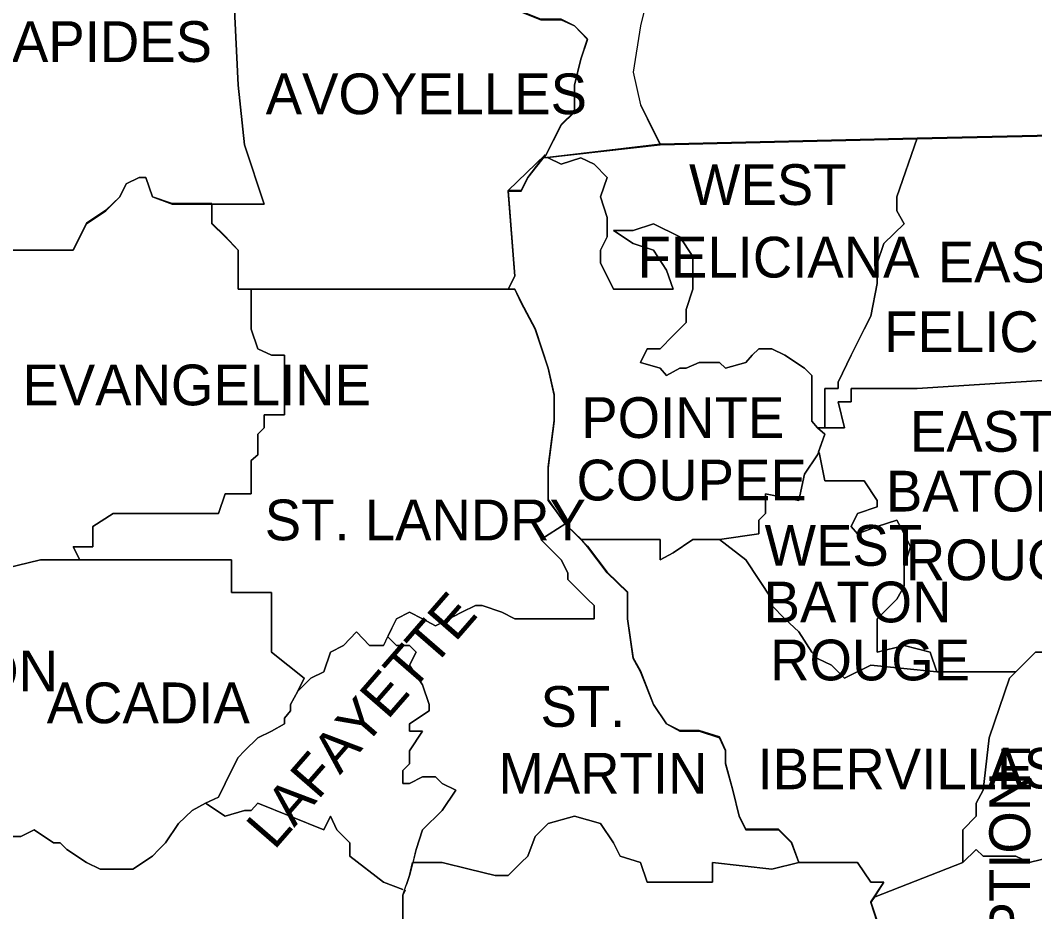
# Model space of a CAD drawing. Extents: x 0.19 to 2.82, y 0.04 to 1.79.
# Drawn here: x 2.3204 to 2.4368, y 1.4916 to 1.594 of the extents above; entities that cross this region are included whole.
import ezdxf

# ---------------------------------------------------------------- set-up
doc = ezdxf.new("R2010")
doc.units = 0
for name, color, linetype in [('Dist03', 7, 'Continuous'), ('Dist08', 7, 'Continuous'), ('Dist58', 7, 'Continuous'), ('Dist61', 7, 'Continuous'), ('Standard Info', 7, 'Continuous')]:
    doc.layers.add(name, color=color, linetype=linetype)

msp = doc.modelspace()

# ---------------------------------------------------------------- linework, layer by layer
at = {"layer": 'Dist03'}
for points in [[(2.3469, 1.56308), (2.3454, 1.56308), (2.3454, 1.56758), (2.3439, 1.56917), (2.3424, 1.57067), (2.3424, 1.57292), (2.34015, 1.57292), (2.33782, 1.57292), (2.33557, 1.57367), (2.33482, 1.57592), (2.33407, 1.57592), (2.33257, 1.57517), (2.33182, 1.57367), (2.33024, 1.57217), (2.32799, 1.57067), (2.32649, 1.56758), (2.31899, 1.56758)], [(2.37715, 1.56308), (2.3469, 1.56308)], [(2.3829, 1.53617), (2.38099, 1.53892), (2.38099, 1.54267), (2.38165, 1.548), (2.38165, 1.551), (2.38099, 1.554), (2.37949, 1.55858), (2.3779, 1.56158), (2.37715, 1.56308)], [(2.40974, 1.49725), (2.4089, 1.49958), (2.4074, 1.50108), (2.40365, 1.50108), (2.4029, 1.50258), (2.40215, 1.50558), (2.40132, 1.50867), (2.40132, 1.51017), (2.40065, 1.51167), (2.39832, 1.51242), (2.39607, 1.51242), (2.39457, 1.51317), (2.39307, 1.51542), (2.39157, 1.51925), (2.39074, 1.52075), (2.39007, 1.52525), (2.39007, 1.52833), (2.38774, 1.53058), (2.38549, 1.53358), (2.38474, 1.53433)], [(2.41899, 1.48975), (2.41799, 1.49275), (2.41949, 1.495), (2.41799, 1.495), (2.41649, 1.49725), (2.40974, 1.49725)]]:
    msp.add_lwpolyline(points, dxfattribs=at)
at = {"layer": 'Dist08'}
for points in [[(2.38057, 1.57817), (2.38249, 1.582), (2.38399, 1.5835), (2.38399, 1.5865), (2.38474, 1.5895), (2.38549, 1.59183), (2.38399, 1.59333), (2.38249, 1.59408), (2.38015, 1.59408), (2.3764, 1.59558), (2.37415, 1.59783), (2.37349, 1.59875)], [(2.3764, 1.57442), (2.3779, 1.57442), (2.37865, 1.57592), (2.38065, 1.5785)], [(2.30232, 1.56758), (2.32649, 1.56758), (2.32799, 1.57067), (2.33024, 1.57217), (2.33182, 1.57367), (2.33257, 1.57517), (2.33407, 1.57592), (2.33482, 1.57592), (2.33557, 1.57367), (2.33782, 1.57292), (2.34015, 1.57292), (2.3424, 1.57292)], [(2.3764, 1.56308), (2.37715, 1.56458), (2.3764, 1.57442)], [(2.3424, 1.57292), (2.3424, 1.57067), (2.3439, 1.56917), (2.3454, 1.56758), (2.3454, 1.56308), (2.3764, 1.56308)]]:
    msp.add_lwpolyline(points, dxfattribs=at)
at = {"layer": 'Dist58'}
for points in [[(2.40882, 1.63942), (2.40665, 1.63567), (2.40515, 1.63192), (2.40515, 1.62808), (2.40215, 1.62508), (2.39982, 1.62058), (2.39982, 1.613), (2.39907, 1.61), (2.39757, 1.60692), (2.39682, 1.60467), (2.39457, 1.60092), (2.39307, 1.59942), (2.39157, 1.59333), (2.39074, 1.588), (2.39157, 1.58425), (2.39232, 1.58275), (2.39382, 1.57975)], [(2.38057, 1.57817), (2.38249, 1.582), (2.38399, 1.5835), (2.38399, 1.5865), (2.38474, 1.5895), (2.38549, 1.59183), (2.38399, 1.59333), (2.38249, 1.59408), (2.38015, 1.59408), (2.3764, 1.59558), (2.37415, 1.59783), (2.37349, 1.59875)], [(2.39382, 1.57975), (2.38057, 1.57817)]]:
    msp.add_lwpolyline(points, dxfattribs=at)
at = {"layer": 'Dist61'}
msp.add_line((2.3764, 1.57442), (2.38065, 1.5785), dxfattribs=at)
for points in [[(2.44915, 1.581), (2.42332, 1.58042)], [(2.39382, 1.57975), (2.38057, 1.57817)], [(2.42332, 1.58042), (2.39382, 1.57975)], [(2.38065, 1.5785), (2.37865, 1.57592), (2.3779, 1.57442), (2.3764, 1.57442)], [(2.38049, 1.57825), (2.37865, 1.57592), (2.3779, 1.57442), (2.3764, 1.57442)], [(2.3764, 1.57442), (2.37715, 1.56458), (2.3764, 1.56308)], [(2.37715, 1.56308), (2.3779, 1.56158), (2.37949, 1.55858), (2.38099, 1.554), (2.38165, 1.551), (2.38165, 1.548), (2.38099, 1.54267), (2.38099, 1.53892), (2.3829, 1.53617)], [(2.38299, 1.53617), (2.38324, 1.53583), (2.38482, 1.53433)], [(2.38474, 1.53433), (2.38549, 1.53358), (2.38774, 1.53058), (2.39007, 1.52833), (2.39007, 1.52525), (2.39074, 1.52075), (2.39157, 1.51925), (2.39307, 1.51542), (2.39457, 1.51317), (2.39607, 1.51242), (2.39832, 1.51242), (2.40065, 1.51167), (2.40132, 1.51017), (2.40132, 1.50867), (2.40215, 1.50558), (2.4029, 1.50258), (2.40365, 1.50108), (2.4074, 1.50108), (2.4089, 1.49958), (2.40974, 1.49725)], [(2.40974, 1.49725), (2.41649, 1.49725), (2.41799, 1.495), (2.41949, 1.495), (2.41799, 1.49275), (2.41899, 1.48975)]]:
    msp.add_lwpolyline(points, dxfattribs=at)
at = {"layer": 'Standard Info'}
for p, q in [((2.42332, 1.58042), (2.42332, 1.58033)), ((2.37715, 1.56308), (2.3764, 1.56308)), ((2.38482, 1.53433), (2.38474, 1.53433))]:
    msp.add_line(p, q, dxfattribs=at)
for points in [[(2.40882, 1.63942), (2.40665, 1.63567), (2.40515, 1.63183), (2.40515, 1.62808), (2.40215, 1.62508), (2.39982, 1.6205), (2.39982, 1.61292), (2.39907, 1.60992), (2.39757, 1.60692), (2.39682, 1.60458), (2.39457, 1.60083), (2.39307, 1.59933), (2.39157, 1.59333), (2.39074, 1.588), (2.39157, 1.58425), (2.39232, 1.58267), (2.39382, 1.57967)], [(2.35815, 1.605), (2.35374, 1.60233), (2.35224, 1.60158), (2.35074, 1.60158), (2.3499, 1.60158), (2.3484, 1.60392), (2.3469, 1.60392), (2.3454, 1.60233), (2.34465, 1.60233), (2.3454, 1.5865), (2.34615, 1.57967), (2.3484, 1.57283), (2.3424, 1.57283)], [(2.3424, 1.57283), (2.3484, 1.57283), (2.34615, 1.57967), (2.3454, 1.5865), (2.34465, 1.60233), (2.3454, 1.60233), (2.3469, 1.60392), (2.3484, 1.60392), (2.3499, 1.60158), (2.35074, 1.60158), (2.35224, 1.60158), (2.35374, 1.60233), (2.35815, 1.605)], [(2.35815, 1.605), (2.35982, 1.60392), (2.36132, 1.60158), (2.36207, 1.60008), (2.36357, 1.59858), (2.36432, 1.59708), (2.36582, 1.59633), (2.36732, 1.59783), (2.36657, 1.59933), (2.36807, 1.60083), (2.3719, 1.60083), (2.37415, 1.59783), (2.3764, 1.5955), (2.38015, 1.594), (2.38249, 1.594), (2.38399, 1.59333), (2.38549, 1.59175), (2.38474, 1.5895), (2.38399, 1.5865), (2.38399, 1.58342), (2.38249, 1.58192), (2.38065, 1.57833)], [(2.38057, 1.57817), (2.38249, 1.58192), (2.38399, 1.58342), (2.38399, 1.5865), (2.38474, 1.5895), (2.38549, 1.59175), (2.38399, 1.59333), (2.38249, 1.594), (2.38015, 1.594), (2.3764, 1.5955), (2.37415, 1.59783), (2.37349, 1.59867)], [(2.42332, 1.58033), (2.44915, 1.58092)], [(2.39382, 1.57967), (2.38057, 1.57817)], [(2.38057, 1.57817), (2.39382, 1.57967)], [(2.39382, 1.57967), (2.42332, 1.58033)], [(2.42332, 1.58042), (2.42099, 1.57367), (2.42099, 1.57208), (2.42182, 1.57058), (2.41949, 1.56833), (2.41874, 1.56608), (2.41874, 1.56375), (2.41799, 1.56), (2.41724, 1.5585), (2.41574, 1.5555), (2.41424, 1.55242), (2.41424, 1.55167), (2.41274, 1.55167), (2.41274, 1.54942), (2.41274, 1.54717)], [(2.41274, 1.54717), (2.41274, 1.54942), (2.41274, 1.55167), (2.41424, 1.55167), (2.41424, 1.55242), (2.41574, 1.5555), (2.41724, 1.5585), (2.41799, 1.56), (2.41874, 1.56375), (2.41874, 1.56608), (2.41949, 1.56833), (2.42182, 1.57058), (2.42099, 1.57208), (2.42099, 1.57367), (2.42332, 1.58042)], [(2.38065, 1.57842), (2.37865, 1.57592), (2.3779, 1.57433), (2.3764, 1.57433)], [(2.3764, 1.57433), (2.3779, 1.57433), (2.37865, 1.57592), (2.38049, 1.57825)], [(2.38774, 1.57133), (2.38699, 1.57367), (2.38774, 1.57592), (2.38624, 1.57742), (2.38474, 1.57817), (2.38249, 1.57742), (2.38099, 1.57817)], [(2.38099, 1.57817), (2.38249, 1.57742), (2.38474, 1.57817), (2.38624, 1.57742), (2.38774, 1.57592), (2.38699, 1.57367), (2.38774, 1.57133)], [(2.3424, 1.57283), (2.34015, 1.57283), (2.33782, 1.57283), (2.33557, 1.57367), (2.33482, 1.57592), (2.33407, 1.57592), (2.33257, 1.57517), (2.33182, 1.57367), (2.33024, 1.57208), (2.32799, 1.57058), (2.32649, 1.56758), (2.30232, 1.56758)], [(2.31899, 1.56758), (2.32649, 1.56758), (2.32799, 1.57058), (2.33024, 1.57208), (2.33182, 1.57367), (2.33257, 1.57517), (2.33407, 1.57592), (2.33482, 1.57592), (2.33557, 1.57367), (2.33782, 1.57283), (2.34015, 1.57283), (2.3424, 1.57283), (2.3424, 1.57058), (2.3439, 1.56908), (2.3454, 1.56758), (2.3454, 1.56308), (2.3469, 1.56308)], [(2.3764, 1.57433), (2.37715, 1.56458), (2.3764, 1.56308)], [(2.3764, 1.56308), (2.37715, 1.56458), (2.3764, 1.57433)], [(2.3764, 1.56308), (2.3454, 1.56308), (2.3454, 1.56758), (2.3439, 1.56908), (2.3424, 1.57058), (2.3424, 1.57283)], [(2.38849, 1.56983), (2.39074, 1.56833), (2.39307, 1.56758), (2.39457, 1.56525), (2.39532, 1.56308), (2.39382, 1.56308), (2.39007, 1.56308), (2.38849, 1.56308), (2.38774, 1.56458), (2.38699, 1.56608), (2.38699, 1.56758), (2.38774, 1.56908), (2.38774, 1.57133)], [(2.38774, 1.57133), (2.38774, 1.56908), (2.38699, 1.56758), (2.38699, 1.56608), (2.38774, 1.56458), (2.38849, 1.56308), (2.39007, 1.56308), (2.39382, 1.56308), (2.39532, 1.56308), (2.39457, 1.56525), (2.39307, 1.56758), (2.39074, 1.56833), (2.38849, 1.56983)], [(2.4119, 1.54717), (2.41124, 1.54792), (2.41124, 1.55017), (2.41124, 1.55317), (2.4104, 1.554), (2.40815, 1.5555), (2.40665, 1.55625), (2.40515, 1.55625), (2.4044, 1.5555), (2.40365, 1.55467), (2.40132, 1.554), (2.40065, 1.55467), (2.39832, 1.55467), (2.39682, 1.554), (2.39607, 1.554), (2.39457, 1.55317), (2.39382, 1.554), (2.39157, 1.55467), (2.39232, 1.55625), (2.39382, 1.55625), (2.39532, 1.55775), (2.39682, 1.55925), (2.39682, 1.56075), (2.39757, 1.56308), (2.39757, 1.56683), (2.39607, 1.56908), (2.39307, 1.57058), (2.39074, 1.56983), (2.38849, 1.56983)], [(2.38849, 1.56983), (2.39074, 1.56983), (2.39307, 1.57058), (2.39607, 1.56908), (2.39757, 1.56683), (2.39757, 1.56308), (2.39682, 1.56075), (2.39682, 1.55925), (2.39532, 1.55775), (2.39382, 1.55625), (2.39232, 1.55625), (2.39157, 1.55467), (2.39382, 1.554), (2.39457, 1.55317), (2.39607, 1.554), (2.39682, 1.554), (2.39832, 1.55467), (2.40065, 1.55467), (2.40132, 1.554), (2.40365, 1.55467), (2.4044, 1.5555), (2.40515, 1.55625), (2.40665, 1.55625), (2.40815, 1.5555), (2.4104, 1.554), (2.41124, 1.55317), (2.41124, 1.55017), (2.41124, 1.54792), (2.4119, 1.54717), (2.41274, 1.54642), (2.4119, 1.54408), (2.4104, 1.54183), (2.40974, 1.53883), (2.4059, 1.53958), (2.4059, 1.53733), (2.40515, 1.53658), (2.40515, 1.535), (2.40065, 1.53433)], [(2.3469, 1.56308), (2.3469, 1.5585), (2.34765, 1.55625), (2.34924, 1.5555), (2.35074, 1.5555), (2.35074, 1.54867), (2.3484, 1.54867), (2.3484, 1.54717), (2.34765, 1.54642), (2.34765, 1.54408), (2.3469, 1.54342), (2.3469, 1.53958), (2.3439, 1.53958), (2.34315, 1.53733), (2.33107, 1.53733), (2.32874, 1.53583), (2.32874, 1.5335), (2.32649, 1.5335), (2.32724, 1.532)], [(2.32724, 1.532), (2.32649, 1.5335), (2.32874, 1.5335), (2.32874, 1.53583), (2.33107, 1.53733), (2.34315, 1.53733), (2.3439, 1.53958), (2.3469, 1.53958), (2.3469, 1.54342), (2.34765, 1.54408), (2.34765, 1.54642), (2.3484, 1.54717), (2.3484, 1.54867), (2.35074, 1.54867), (2.35074, 1.5555), (2.34924, 1.5555), (2.34765, 1.55625), (2.3469, 1.5585), (2.3469, 1.56308)], [(2.3469, 1.56308), (2.37715, 1.56308)], [(2.37715, 1.56308), (2.3779, 1.5615), (2.37949, 1.5585), (2.38099, 1.554), (2.38165, 1.55092), (2.38165, 1.54792), (2.38099, 1.54258), (2.38099, 1.53883), (2.3829, 1.53617)], [(2.38474, 1.53433), (2.38324, 1.53583), (2.38099, 1.53883), (2.38099, 1.54258), (2.38165, 1.54792), (2.38165, 1.55092), (2.38099, 1.554), (2.37949, 1.5585), (2.3779, 1.5615), (2.37715, 1.56308)], [(2.4119, 1.54717), (2.41499, 1.54717), (2.41424, 1.55017), (2.41574, 1.55017), (2.41574, 1.55167), (2.42332, 1.55167), (2.43465, 1.55242), (2.44674, 1.55317)], [(2.44674, 1.55317), (2.43465, 1.55242), (2.42332, 1.55167), (2.41574, 1.55167), (2.41574, 1.55017), (2.41424, 1.55017), (2.41499, 1.54717), (2.41274, 1.54717)], [(2.41274, 1.54717), (2.4119, 1.54717)], [(2.41199, 1.54442), (2.41274, 1.54642), (2.4119, 1.54717)], [(2.40065, 1.53433), (2.40515, 1.535), (2.40515, 1.53658), (2.4059, 1.53733), (2.4059, 1.53958), (2.40974, 1.53883), (2.4104, 1.54183), (2.4119, 1.54408), (2.41199, 1.54433)], [(2.41207, 1.54433), (2.41274, 1.54108), (2.41724, 1.54108), (2.41874, 1.53883), (2.41874, 1.53808), (2.41649, 1.53733), (2.41574, 1.53583), (2.41649, 1.535), (2.41874, 1.53583), (2.42099, 1.53658), (2.42182, 1.535), (2.42257, 1.5335), (2.42182, 1.53125), (2.42182, 1.529), (2.42099, 1.5275), (2.41874, 1.52525), (2.41874, 1.52442), (2.41874, 1.52292), (2.41874, 1.52142), (2.42182, 1.52217), (2.42482, 1.52142), (2.42557, 1.51917)], [(2.42557, 1.51917), (2.42482, 1.52142), (2.42182, 1.52217), (2.41874, 1.52142), (2.41874, 1.52292), (2.41874, 1.52442), (2.41874, 1.52525), (2.42099, 1.5275), (2.42182, 1.529), (2.42182, 1.53125), (2.42257, 1.5335), (2.42182, 1.535), (2.42099, 1.53658), (2.41874, 1.53583), (2.41649, 1.535), (2.41574, 1.53583), (2.41649, 1.53733), (2.41874, 1.53808), (2.41874, 1.53883), (2.41724, 1.54108), (2.41274, 1.54108), (2.41207, 1.54433)], [(2.38299, 1.53617), (2.38015, 1.53433), (2.38249, 1.532), (2.38324, 1.5305), (2.38324, 1.52975), (2.38549, 1.5275), (2.38624, 1.52675), (2.38624, 1.52525), (2.37715, 1.52525), (2.37565, 1.526), (2.3734, 1.52675), (2.37265, 1.52675), (2.37107, 1.526), (2.36807, 1.52442), (2.36657, 1.52525), (2.36507, 1.526), (2.36357, 1.52525), (2.36282, 1.52375), (2.36207, 1.52217), (2.36049, 1.52217), (2.35899, 1.52375), (2.35749, 1.52217), (2.35599, 1.52142), (2.35524, 1.51917), (2.35374, 1.51842), (2.35224, 1.51692)], [(2.36257, 1.52317), (2.36357, 1.52525), (2.36507, 1.526), (2.36657, 1.52525), (2.36807, 1.52442), (2.37107, 1.526), (2.37265, 1.52675), (2.3734, 1.52675), (2.37565, 1.526), (2.37715, 1.52525), (2.38624, 1.52525), (2.38624, 1.52675), (2.38549, 1.5275), (2.38324, 1.52975), (2.38324, 1.5305), (2.38249, 1.532), (2.38015, 1.53433), (2.38299, 1.53617)], [(2.38299, 1.53617), (2.38324, 1.53583), (2.38482, 1.53433)], [(2.38474, 1.53433), (2.38549, 1.5335), (2.38774, 1.5305), (2.39007, 1.52825), (2.39007, 1.52525), (2.39074, 1.52067), (2.39157, 1.51917), (2.39307, 1.51542), (2.39457, 1.51317), (2.39607, 1.51233), (2.39832, 1.51233), (2.40065, 1.51158), (2.40132, 1.51008), (2.40132, 1.50858), (2.40215, 1.50558), (2.4029, 1.50258), (2.40365, 1.501), (2.4074, 1.501), (2.4089, 1.4995), (2.40974, 1.49725)], [(2.40065, 1.53433), (2.39757, 1.53433), (2.39532, 1.53283), (2.39382, 1.532), (2.39382, 1.53433), (2.38474, 1.53433)], [(2.40065, 1.53433), (2.39757, 1.53433), (2.39532, 1.53283), (2.39382, 1.532), (2.39382, 1.53433), (2.38474, 1.53433)], [(2.38474, 1.53433), (2.39382, 1.53433), (2.39382, 1.532), (2.39532, 1.53283), (2.39757, 1.53433), (2.40065, 1.53433)], [(2.4184, 1.49333), (2.41949, 1.495), (2.41799, 1.495), (2.41649, 1.49725), (2.40974, 1.49725), (2.4089, 1.4995), (2.4074, 1.501), (2.40365, 1.501), (2.4029, 1.50258), (2.40215, 1.50558), (2.40132, 1.50858), (2.40132, 1.51008), (2.40065, 1.51158), (2.39832, 1.51233), (2.39607, 1.51233), (2.39457, 1.51317), (2.39307, 1.51542), (2.39157, 1.51917), (2.39074, 1.52067), (2.39007, 1.52525), (2.39007, 1.52825), (2.38774, 1.5305), (2.38549, 1.5335), (2.38482, 1.53433)], [(2.40065, 1.53433), (2.40365, 1.532), (2.40515, 1.52975), (2.40665, 1.5275), (2.40665, 1.52675), (2.40815, 1.52525), (2.40974, 1.52375), (2.41124, 1.52142), (2.4119, 1.52067), (2.41349, 1.51992), (2.41499, 1.51842), (2.41799, 1.51992), (2.42557, 1.51917)], [(2.43465, 1.51917), (2.42557, 1.51917), (2.41799, 1.51992), (2.41499, 1.51842), (2.41349, 1.51992), (2.4119, 1.52067), (2.41124, 1.52142), (2.40974, 1.52375), (2.40815, 1.52525), (2.40665, 1.52675), (2.40665, 1.5275), (2.40515, 1.52975), (2.40365, 1.532), (2.40065, 1.53433)], [(2.40065, 1.53433), (2.40365, 1.532), (2.40515, 1.52975), (2.40665, 1.5275), (2.40665, 1.52675), (2.40815, 1.52525), (2.40974, 1.52375), (2.41124, 1.52142), (2.4119, 1.52067), (2.41349, 1.51992), (2.41499, 1.51842), (2.41799, 1.51992), (2.42557, 1.51917), (2.43465, 1.51917)], [(2.32724, 1.532), (2.32274, 1.532), (2.31749, 1.53075)], [(2.31749, 1.53075), (2.32274, 1.532), (2.32799, 1.532), (2.34465, 1.532), (2.34465, 1.52825), (2.34924, 1.52825), (2.34924, 1.52142), (2.35299, 1.51842), (2.35224, 1.51692)], [(2.35224, 1.51692), (2.35299, 1.51842), (2.34924, 1.52142), (2.34924, 1.52825), (2.34465, 1.52825), (2.34465, 1.532), (2.32724, 1.532)], [(2.34165, 1.50408), (2.34315, 1.50475), (2.3439, 1.50633), (2.34465, 1.50783), (2.3454, 1.50933), (2.34615, 1.51008), (2.34765, 1.51158), (2.34924, 1.51233), (2.35074, 1.51317), (2.35074, 1.51383), (2.3514, 1.51467), (2.3514, 1.51542), (2.35224, 1.51692), (2.35374, 1.51842), (2.35524, 1.51917), (2.35599, 1.52142), (2.35749, 1.52217), (2.35899, 1.52375), (2.36049, 1.52217), (2.36207, 1.52217), (2.36257, 1.52317)], [(2.36257, 1.52317), (2.36357, 1.52217), (2.36507, 1.52217), (2.36582, 1.52142), (2.36507, 1.51992), (2.36657, 1.51767), (2.36732, 1.51542), (2.36732, 1.51467), (2.36507, 1.51317), (2.36507, 1.51233), (2.36657, 1.51233), (2.36507, 1.51008), (2.36507, 1.50858), (2.36432, 1.50783), (2.36432, 1.50633), (2.36507, 1.50633), (2.36657, 1.50708), (2.36807, 1.50708), (2.36882, 1.50633), (2.3704, 1.50558), (2.36882, 1.50325), (2.36657, 1.501), (2.36582, 1.49875), (2.36507, 1.49575), (2.36474, 1.49475)], [(2.36549, 1.49725), (2.36582, 1.49875), (2.36657, 1.501), (2.36882, 1.50325), (2.3704, 1.50558), (2.36882, 1.50633), (2.36807, 1.50708), (2.36657, 1.50708), (2.36507, 1.50633), (2.36432, 1.50633), (2.36432, 1.50783), (2.36507, 1.50858), (2.36507, 1.51008), (2.36657, 1.51233), (2.36507, 1.51233), (2.36507, 1.51317), (2.36732, 1.51467), (2.36732, 1.51542), (2.36657, 1.51767), (2.36507, 1.51992), (2.36582, 1.52142), (2.36507, 1.52217), (2.36357, 1.52217), (2.36257, 1.52317)], [(2.42857, 1.49725), (2.42857, 1.4995), (2.42857, 1.501), (2.43007, 1.50258), (2.43007, 1.50408), (2.4309, 1.50558), (2.43157, 1.51158), (2.4339, 1.51842), (2.4369, 1.52142), (2.44524, 1.52142)], [(2.44524, 1.52142), (2.4369, 1.52142), (2.43465, 1.51917)], [(2.43465, 1.51917), (2.42557, 1.51917)], [(2.43465, 1.51917), (2.4339, 1.51842), (2.43157, 1.51158), (2.4309, 1.50558), (2.43007, 1.50408), (2.43007, 1.50258), (2.42857, 1.501), (2.42857, 1.4995), (2.42857, 1.49725)], [(2.35224, 1.51692), (2.3514, 1.51542), (2.3514, 1.51467), (2.35074, 1.51383), (2.35074, 1.51317), (2.34924, 1.51233), (2.34765, 1.51158), (2.34615, 1.51008), (2.3454, 1.50933), (2.34465, 1.50783), (2.3439, 1.50633), (2.34315, 1.50475), (2.34165, 1.50408), (2.34015, 1.50325), (2.33857, 1.50175), (2.33707, 1.4995), (2.33632, 1.49875), (2.33557, 1.498), (2.33332, 1.4965), (2.33182, 1.4965), (2.32957, 1.4965), (2.32799, 1.49725), (2.32574, 1.49875), (2.32499, 1.4995), (2.32424, 1.4995), (2.32199, 1.501), (2.32049, 1.50025), (2.31765, 1.50025)], [(2.4634, 1.50633), (2.44524, 1.50258), (2.44215, 1.50258), (2.44215, 1.50025), (2.44149, 1.50025), (2.43915, 1.498), (2.43615, 1.49725), (2.43465, 1.498), (2.4339, 1.498), (2.4324, 1.498), (2.4309, 1.498), (2.43007, 1.49875), (2.42857, 1.49725)], [(2.31765, 1.50025), (2.32049, 1.50025), (2.32199, 1.501), (2.32424, 1.4995), (2.32499, 1.4995), (2.32574, 1.49875), (2.32799, 1.49725), (2.32957, 1.4965), (2.33182, 1.4965), (2.33332, 1.4965), (2.33557, 1.498), (2.33632, 1.49875), (2.33707, 1.4995), (2.33857, 1.50175), (2.34015, 1.50325), (2.34165, 1.50408)], [(2.34165, 1.50408), (2.3439, 1.50258), (2.34615, 1.50325), (2.3469, 1.50325), (2.34765, 1.50408), (2.35524, 1.501), (2.35599, 1.50258), (2.35674, 1.501), (2.35824, 1.4995), (2.35824, 1.498), (2.36207, 1.495), (2.36432, 1.49417)], [(2.36432, 1.49417), (2.36207, 1.495), (2.35824, 1.498), (2.35824, 1.4995), (2.35674, 1.501), (2.35599, 1.50258), (2.35524, 1.501), (2.34765, 1.50408), (2.3469, 1.50325), (2.34615, 1.50325), (2.3439, 1.50258), (2.34165, 1.50408)], [(2.36549, 1.49725), (2.36882, 1.49725), (2.3719, 1.4965), (2.3749, 1.49575), (2.3764, 1.49575), (2.3779, 1.49725), (2.37865, 1.498), (2.37949, 1.50025), (2.38099, 1.50175), (2.38399, 1.50258), (2.38699, 1.50175), (2.38849, 1.4995), (2.38924, 1.498), (2.39157, 1.49725), (2.39232, 1.495), (2.39982, 1.495), (2.39982, 1.49725), (2.40665, 1.4965), (2.40974, 1.49725)], [(2.40974, 1.49725), (2.40665, 1.4965), (2.39982, 1.49725), (2.39982, 1.495), (2.39232, 1.495), (2.39157, 1.49725), (2.38924, 1.498), (2.38849, 1.4995), (2.38699, 1.50175), (2.38399, 1.50258), (2.38099, 1.50175), (2.37949, 1.50025), (2.37865, 1.498), (2.3779, 1.49725), (2.3764, 1.49575), (2.3749, 1.49575), (2.3719, 1.4965), (2.36882, 1.49725), (2.36549, 1.49725)], [(2.42857, 1.49725), (2.43007, 1.49875), (2.4309, 1.498), (2.4324, 1.498), (2.4339, 1.498), (2.43465, 1.498), (2.43615, 1.49725), (2.43915, 1.498)], [(2.36507, 1.47658), (2.36507, 1.47908), (2.36357, 1.48358), (2.36357, 1.48967), (2.36432, 1.49042), (2.36432, 1.4935), (2.36507, 1.49575), (2.3654, 1.49725)], [(2.40974, 1.49725), (2.41649, 1.49725), (2.41799, 1.495), (2.41949, 1.495), (2.41799, 1.49267), (2.41899, 1.48967)], [(2.41849, 1.49333), (2.42857, 1.49725)], [(2.42857, 1.49725), (2.41849, 1.49333)], [(2.36457, 1.49408), (2.36432, 1.4935), (2.36432, 1.49042), (2.36357, 1.48967), (2.36357, 1.48358), (2.36507, 1.47908), (2.36507, 1.47658)], [(2.4309, 1.46175), (2.4309, 1.46475), (2.4309, 1.46625), (2.43007, 1.4685), (2.43007, 1.47), (2.4309, 1.4715), (2.43007, 1.473), (2.43007, 1.4745), (2.42932, 1.47533), (2.42857, 1.47683), (2.42707, 1.47758), (2.42407, 1.47833), (2.42257, 1.47983), (2.42182, 1.48133), (2.42099, 1.48358), (2.42099, 1.48592), (2.41949, 1.48817), (2.41874, 1.49042), (2.41799, 1.49267), (2.41849, 1.49333)]]:
    msp.add_lwpolyline(points, dxfattribs=at)

# ---------------------------------------------------------------- texts
for s, p in [('RAPIDES', (2.31494, 1.58917)), ('AVOYELLES', (2.34857, 1.58317)), ('WEST', (2.39714, 1.57275)), ('FELICIANA', (2.39125, 1.56442)), ('EAST', (2.42568, 1.56386)), ('FELICIANA', (2.41953, 1.55586)), ('EVANGELINE', (2.32066, 1.54975)), ('POINTE', (2.38478, 1.546)), ('EAST', (2.42249, 1.54442)), ('COUPEE', (2.38423, 1.53883)), ('BATON', (2.41974, 1.53756)), ('ST. LANDRY', (2.34846, 1.53425)), ('WEST', (2.40581, 1.53133)), ('ROUGE', (2.42202, 1.52967)), ('BATON', (2.4057, 1.52483)), ('ROUGE', (2.40645, 1.51817)), ('JEFFERSON', (2.28754, 1.51692)), ('ACADIA', (2.32345, 1.51325)), ('ST.', (2.3801, 1.51283)), ('MARTIN', (2.37527, 1.50517)), ('IBERVILLE', (2.405, 1.50567)), ('ASCENSION', (2.43137, 1.50575))]:
    msp.add_text(s, height=0.004679, dxfattribs=at).set_placement(p)
for s, rotation, p in [('LAFAYETTE', 48.9999, (2.34955, 1.49859)), ('ASSUMPTION', 90.01, (2.43628, 1.4663))]:
    msp.add_text(s, height=0.004679, rotation=rotation, dxfattribs=at).set_placement(p)

doc.saveas('drawing.dxf')
